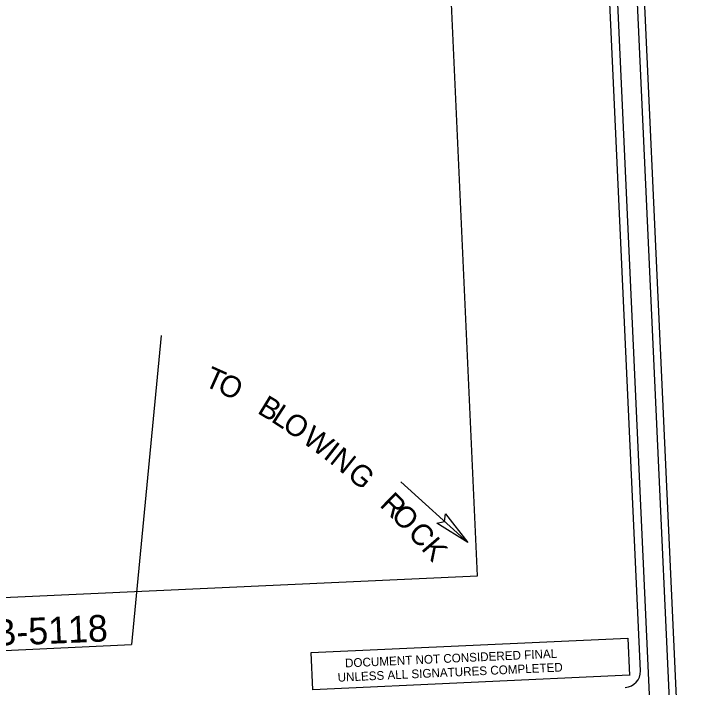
# Model space of a CAD drawing. Extents: x 1190067 to 1192950, y 891516 to 893460.
# Drawn here: x 1192779.3 to 1192950.4, y 893022.3 to 893192.4 of the extents above; entities that cross this region are included whole.
import ezdxf

# ---------------------------------------------------------------- set-up
doc = ezdxf.new("R2010")
doc.units = 0
for name, color, linetype in [('Prop DSN Text', 7, 'Continuous'), ('Prop Terminator CELL', 7, 'Continuous'), ('Scratch_Level_3', 7, 'Continuous'), ('Sheet Plot Border Inside CELL', 7, 'Continuous'), ('Sheet Plot Border Outside CELL', 7, 'Continuous'), ('Sheet Sticker Exception Certification CELL', 7, 'Continuous'), ('Sheet Title CELL', 7, 'Continuous')]:
    doc.layers.add(name, color=color, linetype=linetype)

# ---------------------------------------------------------------- blocks, each defined once
blk = doc.blocks.new('STICKER EXCEPTION CERTIFICATION')
at = {"layer": 'Sheet Sticker Exception Certification CELL'}
for p, q in [((0, -0.47), (0, 0)), ((0, 0), (4.0008, 0)), ((4.0008, -0.0003), (4.0008, -0.4703)), ((4.0008, -0.47), (0, -0.47))]:
    blk.add_line(p, q, dxfattribs=at)
for s, p in [('DOCUMENT NOT CONSIDERED FINAL', (0.4214, -0.2069)), ('UNLESS ALL SIGNATURES COMPLETED', (0.32, -0.3829))]:
    blk.add_text(s, height=0.11, dxfattribs=at).set_placement(p)

msp = doc.modelspace()

# ---------------------------------------------------------------- linework, layer by layer
at = {"layer": 'Prop DSN Text'}
for p, q in [((1192816.57, 893111.1), (1192809.06, 893033.09)), ((1192877.08, 893074.16), (1192893.95, 893058.88)), ((1192691.79, 893027.72), (1192809.06, 893033.09))]:
    msp.add_line(p, q, dxfattribs=at)
at = {"layer": 'Prop Terminator CELL'}
msp.add_lwpolyline([(1192888.32, 893066.07), (1192893.95, 893058.88), (1192886.17, 893063.77), (1192888.09, 893064.18)], close=True, dxfattribs=at)
at = {"layer": 'Scratch_Level_3'}
msp.add_lwpolyline([(1192415.45, 893028.46), (1192896.45, 893050.47), (1192887.89, 893237.54), (1192406.89, 893215.53)], close=True, dxfattribs=at)
at = {"layer": 'Sheet Plot Border Inside CELL'}
msp.add_lwpolyline([(1192282.33, 892915.34), (1192948.23, 892945.8), (1192928.94, 893367.4), (1192263.04, 893336.94)], close=True, dxfattribs=at)
at = {"layer": 'Sheet Plot Border Outside CELL'}
msp.add_lwpolyline([(1192930.33, 893376.46), (1192257.43, 893345.67), (1192277.54, 892906.14), (1192950.44, 892936.92)], close=True, dxfattribs=at)
at = {"layer": 'Sheet Title CELL'}
for points in [[(1192943.01, 892950.6), (1192924.18, 893362.16)], [(1192937.54, 893026.42), (1192922.27, 893360.08)]]:
    msp.add_lwpolyline(points, dxfattribs=at)
msp.add_arc((1192933.54, 893026.26), 4, 272.6195, 2.6195, dxfattribs=at)

# ---------------------------------------------------------------- block references
at = {"layer": 'Sheet Sticker Exception Certification CELL', "xscale": 20.000000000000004, "yscale": 20, "rotation": 2.619466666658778}
msp.add_blockref('STICKER EXCEPTION CERTIFICATION', (1192854.41, 893031.05), dxfattribs=at)

# ---------------------------------------------------------------- texts
at = {"layer": 'Prop DSN Text'}
for s, height, rotation, p in [('T', 5.4, 335.914, (1192827.12, 893098.53)), ('O', 5.4, 334.0599, (1192830.4, 893097.06)), ('B', 5.4, 328.6297, (1192840.58, 893091.67)), ('L', 5.4, 327.0389, (1192844.06, 893089.54)), ('O', 5.4, 325.8877, (1192846.84, 893087.74)), ('W', 5.4, 324.1208, (1192851.89, 893084.27)), ('I', 5.4, 322.0067, (1192857.23, 893080.34)), ('N', 5.4, 321.3339, (1192858.82, 893079.11)), ('G', 5.4, 319.4263, (1192863.24, 893075.53)), ('R', 5.4, 315.7744, (1192871.49, 893068.15)), ('O', 5.4, 314.5293, (1192874.33, 893065.38)), ('C', 5.4, 312.7014, (1192878.59, 893060.99)), ('K', 5.4, 310.7717, (1192882.02, 893057.25)), ('END TIP PROJECT B-5118', 6.75, 2.4356, (1192691.43, 893029.15))]:
    msp.add_text(s, height=height, rotation=rotation, dxfattribs=at).set_placement(p)

doc.saveas('drawing.dxf')
